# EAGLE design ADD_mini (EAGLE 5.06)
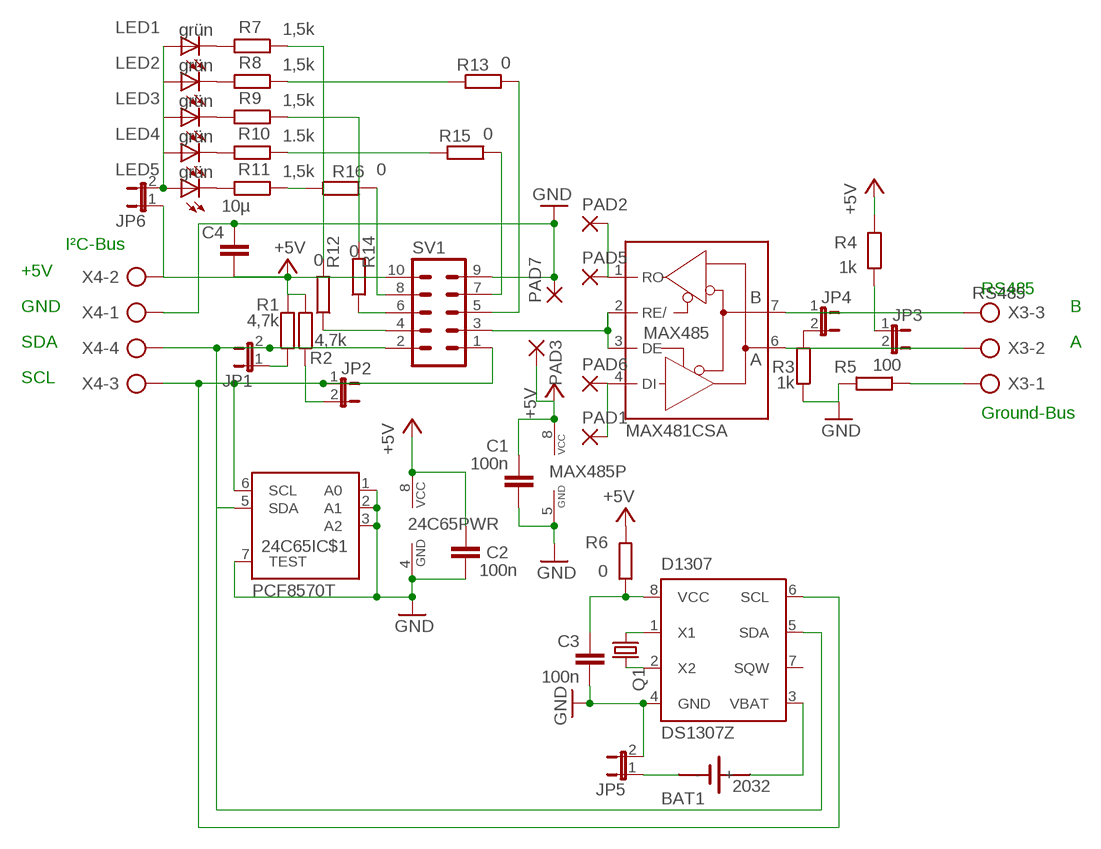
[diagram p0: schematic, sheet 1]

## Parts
24C65  PCF8570T  [SO08]
BAT1  2032  SN2032  [SN2032]
C1  100n  C-EUC0603  [C0603]
C2  100n  C-EUC0603  [C0603]
C3  100n  C-EUC0603  [C0603]
C4  10µ  C-EUC1206K  [C1206K]
D1307  DS1307Z  [SOIC8]
JP1  JP1E  [JP1]
JP2  JP1E  [JP1]
JP3  JP1E  [JP1]
JP4  JP1E  [JP1]
JP5  JP1E  [JP1]
JP6  JP1E  [JP1]
LED1  grün  LED  [SMARTLED-TTW]
LED2  grün  LED  [SMARTLED-TTW]
LED3  grün  LED  [SMARTLED-TTW]
LED4  grün  LED  [SMARTLED-TTW]
LED5  grün  LED  [SMARTLED-TTW]
MAX485  MAX481CSA  [SO08]
PAD1  2,15/1,0  [2,15/1,0]
PAD2  2,15/1,0  [2,15/1,0]
PAD3  2,15/1,0  [2,15/1,0]
PAD5  2,15/1,0  [2,15/1,0]
PAD6  2,15/1,0  [2,15/1,0]
PAD7  2,15/1,0  [2,15/1,0]
Q1  CRYSTALTC38H  [TC38H]
R1  4,7k  R-EU_R0603  [R0603]
R2  4,7k  R-EU_R0603  [R0603]
R3  1k  R-EU_R0603  [R0603]
R4  1k  R-EU_R0603  [R0603]
R5  100  R-EU_R1206  [R1206]
R6  0  R-EU_R1206  [R1206]
R7  1,5k  R-EU_M1206  [M1206]
R8  1,5k  R-EU_M1206  [M1206]
R9  1,5k  R-EU_M1206  [M1206]
R10  1.5k  R-EU_M1206  [M1206]
R11  1,5k  R-EU_M1206  [M1206]
R12  0  R-EU_R1206  [R1206]
R13  0  R-EU_R1206  [R1206]
R14  0  R-EU_R1206  [R1206]
R15  0  R-EU_R1206  [R1206]
R16  0  R-EU_R1206  [R1206]
SV1  ML10L  [ML10L]
X3  RS485  AK500/3  [AK500/3]
X4  I²C-Bus  AK500/4  [AK500/4]

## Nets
+5V: 24C65.8(PWR:VCC) C1.1 C2.1 C4.2 JP6.1 MAX485.8(VCC) PAD3.1(P) R1.2 R2.2 R4.2 R6.2 SV1.10 X4.2
GND: 24C65.1(IC$1:A0) 24C65.2(IC$1:A1) 24C65.3(IC$1:A2) 24C65.4(PWR:GND) 24C65.7(IC$1:TEST) C1.2 C2.2 C3.2 C4.1 D1307.4(GND) JP5.2 MAX485.5(GND) PAD7.1(P) R3.1 R5.2 SV1.9 X4.1
N$2: JP1.1 R1.1
N$3: 24C65.6(IC$1:SCL) D1307.6(SCL) JP2.1 SV1.1 X4.3
N$4: D1307.1(X1) Q1.1
N$6: MAX485.2(RE/) MAX485.3(DE) SV1.3
N$7: MAX485.1(RO) PAD2.1(P) PAD5.1(P)
N$8: MAX485.4(DI) PAD1.1(P) PAD6.1(P)
N$9: JP4.1 MAX485.7(B) X3.3
N$10: R5.1 X3.1
N$11: JP3.2 MAX485.6(A) X3.2
N$12: D1307.2(X2) Q1.2
N$13: JP3.1 R4.1
N$14: JP4.2 R3.2
N$15: 24C65.5(IC$1:SDA) D1307.5(SDA) JP1.2 SV1.2 X4.4
N$16: LED1.C@1(C) R7.2
N$17: JP2.2 R2.1
N$18: BAT1.- JP5.1
N$19: BAT1.+ D1307.3(VBAT)
N$20: LED2.C@1(C) R8.2
N$21: C3.1 D1307.8(VCC) R6.1
N$22: LED3.C@1(C) R9.2
N$23: LED4.C@1(C) R10.2
N$24: LED5.C@1(C) R11.2
N$25: R12.1 SV1.4
N$26: R13.2 SV1.5
N$27: R14.1 SV1.6
N$28: R15.2 SV1.7
N$29: R16.2 SV1.8
N$30: R7.1 R12.2
N$31: R8.1 R13.1
N$32: R9.1 R14.2
N$33: R10.1 R15.1
N$34: R11.1 R16.1
N$35: JP6.2 LED1.A@1(A) LED2.A@1(A) LED3.A@1(A) LED4.A@1(A) LED5.A@1(A)
Unconnected: D1307.7(SQW)

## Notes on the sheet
- I²C-Bus
- +5V
- RS485
- GND | B
- SDA | A
- SCL
- Ground-Bus

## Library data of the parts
24C65 = i2c:PCF8570: 256 x 8-Bit Static Low-Voltage RAM with I²C Bus Interface
BAT1 = sn2032:SN2032: LI BATTERY
C1-C4 = rcl:C-EU: CAPACITOR, European symbol
D1307 = ds1307_pcf8583:DS1307: I2C-Bus CLOCK/CALENDAR
JP1-JP6 = jumper:JP1E: JUMPER
LED1-LED5 = led:LED: LED
MAX485 = maxim:MAX481CSA: RS485 TRANSEIVER
PAD1-PAD3 PAD5-PAD7 = wirepad:2,15/1,0: THROUGH-HOLE PAD
Q1 = crystal:CRYSTAL: CRYSTAL
R1-R16 = rcl:R-EU_: RESISTOR, European symbol
SV1 = con-harting-ml:ML10: HARTING
X3 = con-ptr500:AK500/3: CONNECTOR
X4 = con-ptr500:AK500/4: CONNECTOR

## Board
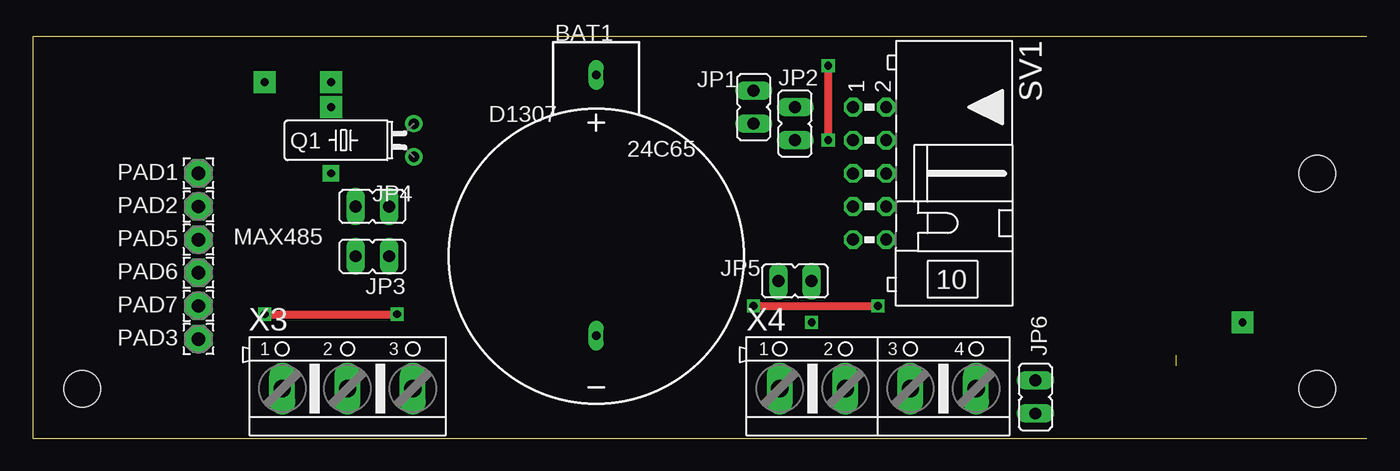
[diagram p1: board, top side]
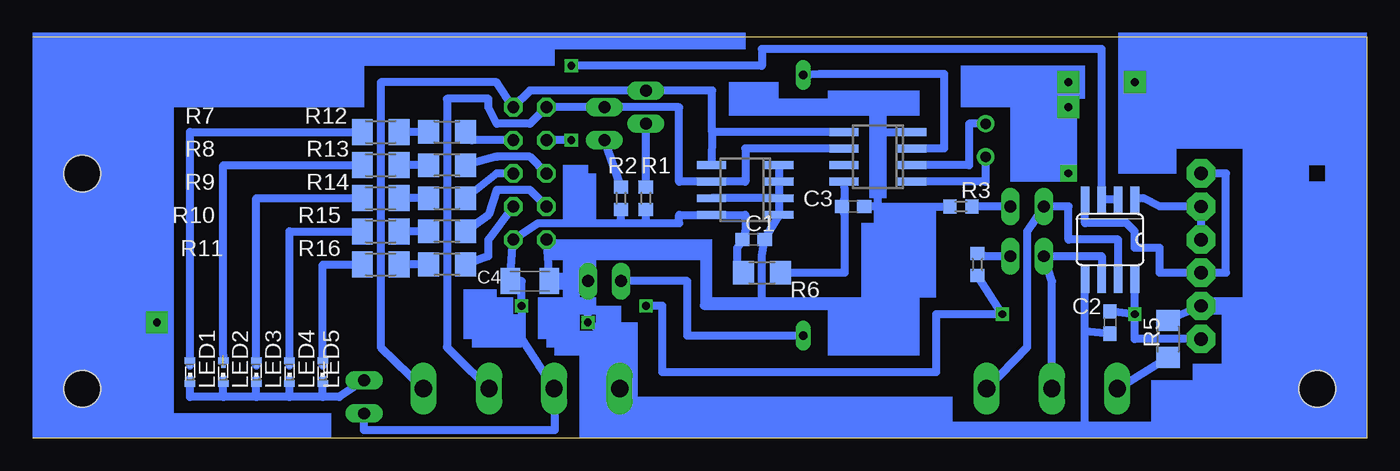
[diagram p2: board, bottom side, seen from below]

Size 102.22 x 30.79 mm. Coordinates in mm from the lower left corner, seen from the top.
Outline: 102.22,0 0,0 0,30.79 102.22,30.79
Copper layers (1*16): Top 0.035mm / dielectric 1.5mm / Bottom 0.035mm
Design rules "default": minimum track width 10mil, minimum drill 24mil, track to track 8mil, track to pad 8mil, pad to pad 8mil, via to via 8mil, smd to smd 8mil, copper to edge 40mil, drill to drill 8mil, minimum pad ring 10mil, minimum via ring 8mil, stop-mask expansion 4mil, vias tented up to drill 0mil, thermal gap 10mil
Holes 2.8 mm at 3.81,3.81 98.42,3.81 98.42,20.32

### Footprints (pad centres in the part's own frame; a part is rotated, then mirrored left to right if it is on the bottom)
SO08 = smd 0.6 x 2.2: 1 -1.905,-2.6; 2 -0.635,-2.6; 3 0.635,-2.6; 4 1.905,-2.6; 5 1.905,2.6; 6 0.635,2.6; 7 -0.635,2.6; 8 -1.905,2.6
SN2032 = drill 0.65 long: + 0,13.9; - 0,-6.1
C0603 = smd 1.1 x 1: 1 -0.85,0; 2 0.85,0
C1206K = smd 1.5 x 2: 1 -1.5,0; 2 1.5,0
SOIC8 = smd 0.6 x 2.2: 1 -1.905,-2.6; 2 -0.635,-2.6; 3 0.635,-2.6; 4 1.905,-2.6; 5 1.905,2.6; 6 0.635,2.6; 7 -0.635,2.6; 8 -1.905,2.6
JP1 = drill 0.914 long: 1 0,-1.27; 2 0,1.27
SMARTLED-TTW = smd 0.8 x 0.5: A 0,-0.875; C 0,0.875 | smd 0.35 x 0.35: A@1 0,-0.5; C@1 0,0.5
SO08' = smd 0.66 x 2.032: 1 -1.905,-3.073; 2 -0.635,-3.073; 3 0.635,-3.073; 4 1.905,-3.073; 5 1.905,3.073; 6 0.635,3.073; 7 -0.635,3.073; 8 -1.905,3.073
2,15/1,0 = drill 1.016 pad 2.159 octagon: 1 0,0
TC38H = drill 0.813 round: 1 -1.27,0; 2 1.27,0
R0603 = smd 1 x 1.1: 1 -0.85,0; 2 0.85,0
R1206 = smd 1.6 x 1.803: 1 -1.422,0; 2 1.422,0
M1206 = smd 1.6 x 2: 1 -1.4,0; 2 1.4,0
ML10L = drill 0.914 octagon: 1 -5.08,-1.27; 2 -5.08,1.27; 3 -2.54,-1.27; 4 -2.54,1.27; 5 0,-1.27; 6 0,1.27; 7 2.54,-1.27; 8 2.54,1.27; 9 5.08,-1.27; 10 5.08,1.27
AK500/3 = drill 1.321 long: 1 -5.004,0; 2 0,0; 3 5.004,0
AK500/4 = drill 1.321 long: 1 -7.518,0; 2 -2.489,0; 3 2.489,0; 4 7.518,0

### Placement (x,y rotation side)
24C65  47.62,19.05 90 bottom
BAT1  43.18,13.97 0 top
C1  46.99,15.24 0 bottom
C2  19.68,8.89 270 bottom
C3  39.37,17.78 0 bottom
C4  64.14,12.06 180 bottom
D1307  37.47,21.59 90 bottom
JP1  55.24,25.4 0 top
JP2  58.42,24.13 180 top
JP3  26.04,13.97 90 top
JP4  26.04,17.78 270 top
JP5  58.42,12.06 270 top
JP6  76.83,3.17 0 top
LED1  90.17,5.08 0 bottom
LED2  87.63,5.08 0 bottom
LED3  85.09,5.08 0 bottom
LED4  82.55,5.08 0 bottom
LED5  80.01,5.08 0 bottom
MAX485  MAX481CSA  [SO08']  19.68,15.24 180 bottom
PAD1  12.7,20.32 0 top
PAD2  12.7,17.78 0 top
PAD3  12.7,7.62 0 top
PAD5  12.7,15.24 0 top
PAD6  12.7,12.7 0 top
PAD7  12.7,10.16 0 top
Q1  29.21,22.86 90 top
R1  55.24,18.41 270 bottom
R2  57.15,18.41 270 bottom
R3  31.11,17.78 0 bottom
R4  29.84,13.34 270 bottom
R5  15.24,7.62 90 bottom
R6  46.35,12.7 180 bottom
R7  75.56,23.5 180 bottom
R8  75.56,20.95 180 bottom
R9  75.56,18.41 180 bottom
R10  75.56,15.88 180 bottom
R11  75.56,13.34 180 bottom
R12  70.48,23.5 180 bottom
R13  70.48,20.95 0 bottom
R14  70.48,18.41 180 bottom
R15  70.48,15.88 0 bottom
R16  70.48,13.34 0 bottom
SV1  64.14,20.32 270 top
X3  24.13,3.81 0 top
X4  64.77,3.81 0 top

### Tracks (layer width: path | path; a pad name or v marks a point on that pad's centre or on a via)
+5V  (via drill 0.6)
  Top 0.61: v17.78,9.53 v27.94,9.53 | v55.24,10.16 v64.77,10.16
  Bottom 0.61: v17.78,9.53 C2.1 | v17.78,9.53 MAX485.8 v17.78,9.53 | v27.94,9.53 R4.2 v27.94,9.53 | v27.94,9.53 33.02,9.53 33.02,5.08 53.98,5.08 53.98,10.16 v55.24,10.16 | 57.15,16.51 63.5,16.51 SV1.10 C4.2 64.77,12.06 v64.77,10.16 64.77,7.62 X4.2 62.23,0.64 76.83,0.64 JP6.1 | 57.15,16.51 55.24,16.51 | 55.24,16.51 52.7,16.51 52.7,17.14 24C65.8 47.62,17.14 47.62,15.88 C1.1 48.26,14.61 48.26,12.7 R6.2 | 55.24,16.51 R1.2 | 57.15,16.51 R2.2 | PAD3.1 17.78,7.62 v17.78,9.53
GND  (via drill 0.6)
  Bottom 0.61: 24C65.4 24C65.3 24C65.2 | 24C65.2 24C65.1 C1.2 46.35,13.97 46.35,10.16 | 24C65.2 24C65.7 | 62.73,13.94 SV1.9 | C4.1 62.73,13.94 | D1307.4 37.47,23.5 37.47,17.78 | 21.59,8.26 C2.2 | 37.47,17.78 R3.1 | 37.47,17.78 C3.2 | C4.1 JP5.2 v59.69,8.89 57.78,7.62 57.15,7.62 57.15,3.81 X4.1 57.15,3.17 57.15,0.64 21.59,0.64 | 62.87,12.06 C4.1 | 21.59,8.26 MAX485.5 | 21.59,0.64 21.59,8.26 | 62.73,13.94 50.8,13.97 50.8,10.16 46.35,10.16 | 46.35,10.16 37.47,10.16 37.47,17.78 | PAD7.1 R5.2 PAD7.1 | PAD7.1 10.79,10.16 10.79,0.64 21.59,0.64
N$1  (via drill 0.6 pad 1.68)
  other vias: 22.86,27.3
N$2
  Bottom 0.61: R1.1 JP1.1
N$3
  Bottom 0.61: D1307.6 47.62,22.23 47.62,19.68 24C65.6 52.7,19.68 52.7,25.4 JP2.1 SV1.1 64.14,24.13 66.67,24.13 67.31,25.4 67.31,26.04 70.48,26.04 70.48,6.99 69.85,6.35 X4.3
N$4
  Bottom 0.61: D1307.1 29.21,19.68 Q1.1
N$5  (via drill 0.6 pad 1.68)
  other vias: 22.86,25.4
N$6  (via drill 0.6)
  Top 0.61: v60.96,28.57 v60.96,22.86
  Bottom 0.61: v60.96,22.86 SV1.3 | MAX485.2 MAX485.3 20.32,29.84 46.35,29.84 46.35,28.57 v60.96,28.57
N$7
  Bottom 0.61: MAX485.1 17.14,18.41 15.88,17.78 PAD2.1 PAD5.1
N$8
  Bottom 0.61: MAX485.4 21.59,16.51 18.41,16.51 17.78,15.88 17.78,14.61 15.88,14.61 15.88,12.7 PAD6.1 10.79,12.7 10.79,20.32 PAD1.1
N$9
  Bottom 0.61: MAX485.7 19.05,15.24 22.86,15.24 22.86,17.78 JP4.1 26.04,15.88 26.04,6.99 X3.3
N$10
  Bottom 0.61: X3.1 R5.1
N$11
  Bottom 0.61: MAX485.6 20.32,13.97 JP3.2 24.13,12.06 X3.2
N$12
  Bottom 0.61: Q1.2 30.48,24.13 30.48,20.95 D1307.2
N$13  (via drill 0.6 pad 1.27)
  Bottom 0.61: R4.1 29.21,13.97 JP3.1
  other vias: 27.3,13.97
N$14
  Bottom 0.61: JP4.2 R3.2
N$15
  Bottom 0.61: D1307.5 50.16,23.5 | 50.16,23.5 24C65.5 | 50.16,23.5 50.16,26.67 JP1.2 64.14,26.67 SV1.2 66.67,27.3 75.56,27.3 75.56,6.99 X4.4
N$16
  Bottom 0.61: LED1.C@1 90.17,23.5 R7.2
N$17
  Bottom 0.61: R2.1 JP2.2
N$18
  Bottom 0.61: BAT1.- 52.07,7.87 52.07,12.06 JP5.1
N$19
  Bottom 0.61: D1307.3 32.38,22.23 32.38,27.94 41.91,27.94 BAT1.+
N$20  (1 unrouted)
  Bottom 0.61: R8.2 87.63,20.95 87.63,6.35
N$21
  Bottom 0.61: D1307.8 40.01,19.05 40.01,18.41 C3.1 40.01,17.14 40.01,12.7 R6.1
N$22
  Bottom 0.61: LED3.C@1 85.09,18.41 R9.2
N$23
  Bottom 0.61: R10.2 82.55,15.88 LED4.C@1
N$24
  Bottom 0.61: LED5.C@1 80.01,13.34 R11.2
N$25
  Bottom 0.61: SV1.4 68.58,22.86 R12.1
N$26
  Bottom 0.61: SV1.5 64.14,21.59 66.67,21.59 R13.2
N$27
  Bottom 0.61: SV1.6 66.67,20.32 R14.1
N$28
  Bottom 0.61: SV1.7 64.14,19.05 66.67,19.05 67.31,17.14 R15.2
N$29
  Bottom 0.61: SV1.8 67.31,15.24 67.31,13.97 R16.2
N$30
  Bottom 0.61: R12.2 R7.1
N$31
  Bottom 0.61: R13.1 72.39,20.95 | 74.3,20.95 R8.1 72.39,20.95 | 72.39,20.95 71.75,20.95
N$32
  Bottom 0.61: R14.2 R9.1
N$33
  Bottom 0.61: R15.1 R10.1
N$34
  Bottom 0.61: R16.1 R11.1
N$35
  Bottom 0.61: LED1.A@1 90.17,3.17 87.63,3.17 | 80.01,3.17 78.74,3.17 JP6.2 | 80.01,3.17 82.55,3.17 | 82.55,3.17 85.09,3.17 | 85.09,3.17 87.63,3.17 | 80.01,3.17 LED5.A@1 | 82.55,3.17 LED4.A@1 | 85.09,3.17 LED3.A@1 | 87.63,3.17 LED2.A@1
N$36  (via drill 0.6 pad 1.27)
  other vias: 22.86,20.32
N$37  (via drill 0.6 pad 1.68)
  other vias: 17.78,27.3
N$38  (via drill 0.6 pad 1.68)
  other vias: 92.71,8.89
(copper drawn outside any net)
  shapes: Bottom area x82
